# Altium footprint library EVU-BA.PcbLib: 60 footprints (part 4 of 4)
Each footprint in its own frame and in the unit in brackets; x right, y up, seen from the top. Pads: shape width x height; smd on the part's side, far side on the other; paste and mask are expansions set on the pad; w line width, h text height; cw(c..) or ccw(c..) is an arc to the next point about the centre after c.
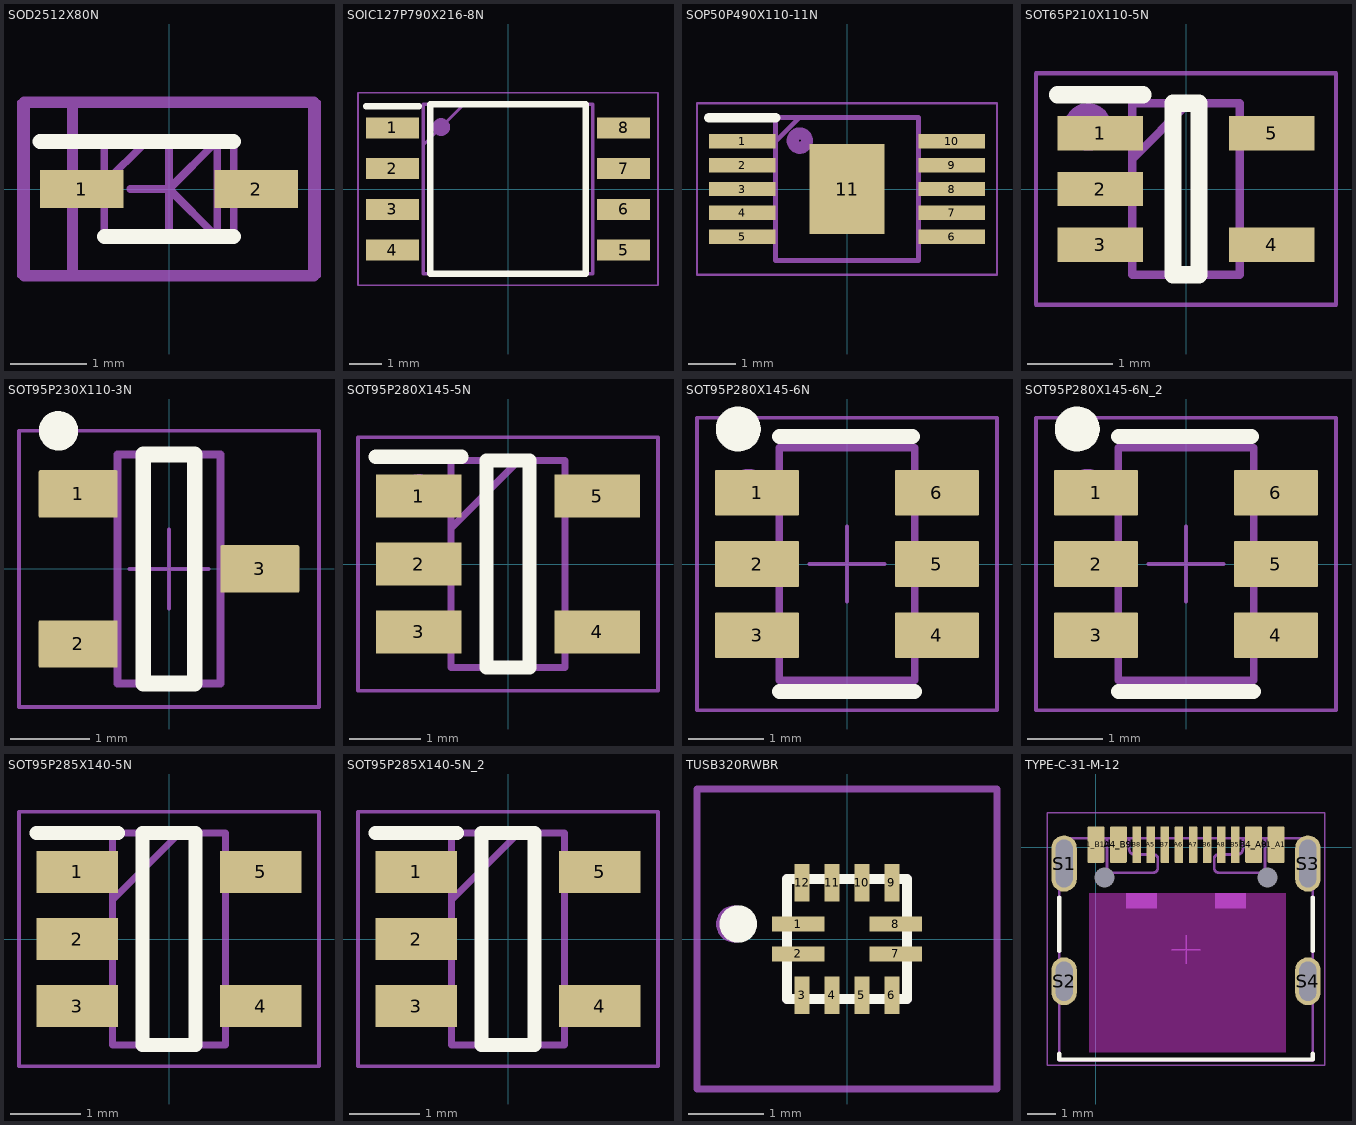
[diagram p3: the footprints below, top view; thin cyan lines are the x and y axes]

## SOD2512X80N [mm]
pads (2):
  rect 1.1x0.5 smd: 1(-1.15,0) 2(1.15,0)
Top Overlay:
  lines w0.2: -1.7,0.625 0.85,0.625 ; -0.85,-0.625 0.85,-0.625
Top Assembly:
  lines w0.1: -0.508,0 0,0 ; 0,-0.635 0,0.635 ; 0.635,0 1.143,0 ; 0,0 0.635,0.635 0.635,-0.635 0,0
  lines w0.15: -1.27,-1.143 -1.27,1.143 ; -1.905,-1.143 1.905,-1.143 1.905,1.143 -1.905,1.143 -1.905,-1.143
Mechanical 13:
  lines w0.1: -0.85,0.075 -0.3,0.625 ; -0.85,-0.625 0.85,-0.625 0.85,0.625 -0.85,0.625 -0.85,-0.625
Top Courtyard:
  lines w0.05: -1.975,-1.15 1.975,-1.15 1.975,1.15 -1.975,1.15 -1.975,-1.15
3D body "BZX84J-B4V7.stp": height 0.8, standoff 0, extent -1.25,-0.625 1.25,0.625

## SOIC127P790X216-8N [mm]
pads (8):
  rect 1.65x0.65 smd: 1(-3.6,1.905) 2(-3.6,0.635) 3(-3.6,-0.635) 4(-3.6,-1.905) 5(3.6,-1.905) 6(3.6,-0.635) 7(3.6,0.635) 8(3.6,1.905)
Top Overlay:
  lines w0.2: -4.425,2.58 -2.775,2.58 ; -2.425,-2.642 2.425,-2.642 2.425,2.642 -2.425,2.642 -2.425,-2.642
Top Assembly:
  circle w0.254: c-2.083,1.93 r0.15
  lines w0.1: -2.642,-2.642 2.642,-2.642 2.642,2.642 -2.642,2.642 -2.642,-2.642
Mechanical 13:
  lines w0.1: -2.642,1.372 -1.372,2.642 ; -2.642,-2.642 2.642,-2.642 2.642,2.642 -2.642,2.642 -2.642,-2.642
Top Courtyard:
  lines w0.05: -4.675,-2.995 4.675,-2.995 4.675,2.995 -4.675,2.995 -4.675,-2.995
3D body "MT25QL128ABA1ESE-0SIT_TR.stp": height 2.16, standoff 0, extent -3.95,-2.642 3.95,2.642

## SOP50P490X110-11N [mm]
pads (11):
  rect 1.4x0.3 smd: 1(-2.2,1) 2(-2.2,0.5) 3(-2.2,0) 4(-2.2,-0.5) 5(-2.2,-1) 6(2.2,-1) 7(2.2,-0.5) 8(2.2,0) 9(2.2,0.5) 10(2.2,1)
  rect 1.57x1.88 smd: 11(0,0)
Top Overlay:
  lines w0.2: -2.9,1.5 -1.5,1.5
Top Assembly:
  circle w0.254: c-0.991,1.016 r0.15
  lines w0.1: -1.5,-1.5 1.5,-1.5 1.5,1.5 -1.5,1.5 -1.5,-1.5
Mechanical 13:
  lines w0.1: -1.5,1 -1,1.5 ; -1.5,-1.5 1.5,-1.5 1.5,1.5 -1.5,1.5 -1.5,-1.5
Top Courtyard:
  lines w0.05: -3.15,-1.8 3.15,-1.8 3.15,1.8 -3.15,1.8 -3.15,-1.8
3D body "TPS54160DGQ.stp": height 0.96, standoff 0, extent -2.463,-1.5 2.463,1.5

## SOT65P210X110-5N [mm]
pads (5):
  rect 1x0.4 smd: 1(-1,0.65) 2(-1,0) 3(-1,-0.65) 4(1,-0.65) 5(1,0.65)
Top Overlay:
  lines w0.2: -1.5,1.1 -0.5,1.1 ; -0.15,-1 -0.15,1 0.15,1 0.15,-1 -0.15,-1
Top Assembly:
  circle w0.254: c-1.145,0.724 r0.15
  lines w0.1: -0.625,-1 -0.625,1 0.625,1 0.625,-1 -0.625,-1
Mechanical 13:
  lines w0.1: -0.625,0.35 0.025,1 ; -0.625,-1 -0.625,1 0.625,1 0.625,-1 -0.625,-1
Top Courtyard:
  lines w0.05: -1.75,-1.35 -1.75,1.35 1.75,1.35 1.75,-1.35 -1.75,-1.35
3D body "ZXRE160H5TA.stp": height 1.1, standoff 0, extent -1.05,-1 1.05,1

## SOT95P230X110-3N [mm] "SOT95P230X110-3N"
height 1.1
pads (3):
  rrect5% 1x0.6 smd mask+0.05: 1(-1.15,0.95) 2(-1.15,-0.95) 3(1.15,0)
Top Overlay:
  circle w0.25: c-1.4,1.75 r0.125
  lines w0.2: -0.325,-1.45 -0.325,1.45 0.325,1.45 0.325,-1.45 -0.325,-1.45
Top Assembly:
  circle w0.254: c-1.143,0.965 r0.15
  lines w0.1: -0.65,-1.45 -0.65,1.45 0.65,1.45 0.65,-1.45 -0.65,-1.45
Top Designator:
  text ".Designator" at -3.378,-0.211 h1.5
Mechanical 9:
  text ".MARK" at 0.329,-1.778 h1.5
Top Courtyard:
  lines w0.05: -0.5,0 0.5,0 ; 0,-0.5 0,0.5 ; -1.9,-1.75 -1.9,1.75 1.9,1.75 1.9,-1.75 -1.9,-1.75
3D body "SOT-23.STEP": height 1.1, standoff 0, extent -1.35,-1.55 1.35,1.55

## SOT95P280X145-5N [mm]
pads (5):
  rect 1.2x0.6 smd: 1(-1.25,0.95) 2(-1.25,0) 3(-1.25,-0.95) 4(1.25,-0.95) 5(1.25,0.95)
Top Overlay:
  lines w0.2: -1.85,1.5 -0.65,1.5 ; -0.3,-1.45 -0.3,1.45 0.3,1.45 0.3,-1.45 -0.3,-1.45
Top Assembly:
  circle w0.254: c-1.249,0.98 r0.15
  lines w0.1: -0.8,-1.45 -0.8,1.45 0.8,1.45 0.8,-1.45 -0.8,-1.45
Mechanical 13:
  lines w0.1: -0.8,0.5 0.15,1.45 ; -0.8,-1.45 -0.8,1.45 0.8,1.45 0.8,-1.45 -0.8,-1.45
Top Courtyard:
  lines w0.05: -2.1,-1.775 -2.1,1.775 2.1,1.775 2.1,-1.775 -2.1,-1.775
3D body "LMV331IDBVR.stp": height 1.2, standoff 0, extent -1.4,-1.45 1.4,1.45

## SOT95P280X145-6N [mm]
pads (6):
  rrect5% 1.12x0.61 smd mask+0.05: 1(-1.2,0.95) 2(-1.2,0) 3(-1.2,-0.95) 4(1.2,-0.95) 5(1.2,0) 6(1.2,0.95)
Top Overlay:
  circle w0.3: c-1.45,1.8 r0.15
  lines w0.2: -0.9,-1.7 0.9,-1.7 ; -0.9,1.7 0.875,1.7
Top Assembly:
  circle w0.254: c-1.317,0.991 r0.15
  lines w0.1: -0.9,-1.55 -0.9,1.55 0.9,1.55 0.9,-1.55 -0.9,-1.55
Top Designator:
  text ".Designator" at -3.25,-0.3 h1.5
Mechanical 9:
  text ".MARK" at 0.45,-1.675 h1.5
Top Courtyard:
  lines w0.05: -0.5,0 0.5,0 ; 0,-0.5 0,0.5 ; -2,-1.95 -2,1.95 2,1.95 2,-1.95 -2,-1.95
3D body "SOT-23-6_DBV.STEP": height 1.45, standoff 0, extent -1.417,-1.55 1.418,1.55
3D body: height 1.46, standoff 1.45, extent -0.498,0.801 0,1.3

## SOT95P280X145-6N_2 [mm]
pads (6):
  rrect5% 1.12x0.61 smd mask+0.05: 1(-1.2,0.95) 2(-1.2,0) 3(-1.2,-0.95) 4(1.2,-0.95) 5(1.2,0) 6(1.2,0.95)
Top Overlay:
  circle w0.3: c-1.45,1.8 r0.15
  lines w0.2: -0.9,-1.7 0.9,-1.7 ; -0.9,1.7 0.875,1.7
Top Assembly:
  circle w0.254: c-1.317,0.991 r0.15
  lines w0.1: -0.9,-1.55 -0.9,1.55 0.9,1.55 0.9,-1.55 -0.9,-1.55
Top Designator:
  text ".Designator" at -3.25,-0.3 h1.5
Mechanical 9:
  text ".MARK" at 0.45,-1.675 h1.5
Top Courtyard:
  lines w0.05: -0.5,0 0.5,0 ; 0,-0.5 0,0.5 ; -2,-1.95 -2,1.95 2,1.95 2,-1.95 -2,-1.95
3D body "SOT-23-6_DBV.STEP": height 1.45, standoff 0, extent -1.417,-1.55 1.418,1.55
3D body: height 1.46, standoff 1.45, extent -0.498,0.801 0,1.3

## SOT95P285X140-5N [mm]
pads (5):
  rect 1.15x0.6 smd: 1(-1.3,0.95) 2(-1.3,0) 3(-1.3,-0.95) 4(1.3,-0.95) 5(1.3,0.95)
Top Overlay:
  lines w0.2: -1.875,1.5 -0.725,1.5 ; -0.375,-1.5 0.375,-1.5 0.375,1.5 -0.375,1.5 -0.375,-1.5
Top Assembly:
  circle w0.254: c-1.254,0.939 r0.15
  lines w0.1: -0.8,-1.5 0.8,-1.5 0.8,1.5 -0.8,1.5 -0.8,-1.5
Mechanical 13:
  lines w0.1: -0.8,0.55 0.15,1.5 ; -0.8,-1.5 0.8,-1.5 0.8,1.5 -0.8,1.5 -0.8,-1.5
Top Courtyard:
  lines w0.05: -2.125,-1.8 2.125,-1.8 2.125,1.8 -2.125,1.8 -2.125,-1.8
3D body "AP2191WG-7.stp": height 1.4, standoff 0, extent -1.425,-1.5 1.425,1.5

## SOT95P285X140-5N_2 [mm]
pads (5):
  rect 1.15x0.6 smd: 1(-1.3,0.95) 2(-1.3,0) 3(-1.3,-0.95) 4(1.3,-0.95) 5(1.3,0.95)
Top Overlay:
  lines w0.2: -1.875,1.5 -0.725,1.5 ; -0.375,-1.5 0.375,-1.5 0.375,1.5 -0.375,1.5 -0.375,-1.5
Top Assembly:
  circle w0.254: c-1.254,0.939 r0.15
  lines w0.1: -0.8,-1.5 0.8,-1.5 0.8,1.5 -0.8,1.5 -0.8,-1.5
Mechanical 13:
  lines w0.1: -0.8,0.55 0.15,1.5 ; -0.8,-1.5 0.8,-1.5 0.8,1.5 -0.8,1.5 -0.8,-1.5
Top Courtyard:
  lines w0.05: -2.125,-1.8 2.125,-1.8 2.125,1.8 -2.125,1.8 -2.125,-1.8
3D body "AP2191WG-7.stp": height 1.4, standoff 0, extent -1.425,-1.5 1.425,1.5

## TUSB320RWBR [mm]
pads (12):
  rect 0.7x0.2 smd: 1(-0.65,0.2) 2(-0.65,-0.2) 7(0.65,-0.2) 8(0.65,0.2)
  rect 0.2x0.5 smd: 3(-0.6,-0.75) 4(-0.2,-0.75) 5(0.2,-0.75) 6(0.6,-0.75) 9(0.6,0.75) 10(0.2,0.75) 11(-0.2,0.75) 12(-0.6,0.75)
Top Overlay:
  lines w0.127: -0.8,-0.8 0.8,-0.8 0.8,0.8 -0.8,0.8 -0.8,-0.8
  lines w0.25: -1.575,0.2 cw(c-1.45,0.2) -1.325,0.2 cw(c-1.45,0.2) -1.575,0.2
Top Assembly:
  circle w0.254: c-1.5,0.2 r0.12
  lines w0.127: -0.8,-0.8 -0.8,0.8 0.8,0.8 0.8,-0.8 -0.8,-0.8
Mechanical 13:
  lines w0.1: -0.8,-0.8 0.8,-0.8 0.8,0.8 -0.8,0.8 -0.8,-0.8
Top Courtyard:
  lines w0.1: -2,-2 2,-2 2,2 -2,2 -2,-2
3D body "TUSB320RWBR.stp": height 0.5, standoff 0, extent -0.8,-0.8 0.8,0.8

## TYPE-C-31-M-12 [mm] "USB TYPE-C 5A 16P Female SMD USB Connectors"
height 3.24
pads (18):
  rrect15% 0.6x1.3 smd mask+0.05: A1_B12(0,0.1) A4_B9(0.8,0.1) B1_A12(6.4,0.1) B4_A9(5.6,0.1)
  rrect15% 0.3x1.3 smd mask+0.05: A5(1.95,0.1) A6(2.95,0.1) A7(3.45,0.1) A8(4.45,0.1) B5(4.95,0.1) B6(3.95,0.1) B7(2.45,0.1) B8(1.45,0.1)
  oval 0.9x2 hole 0.6 slot 1.7 at 90 deg mask+0.05: S1(-1.125,-0.57) S3(7.525,-0.57)
  oval 0.9x1.7 hole 0.6 slot 1.4 at 90 deg mask+0.05: S2(-1.125,-4.75) S4(7.525,-4.75)
  round 0 hole 0.7 unplated: ""(0.31,-1.07) ""(6.09,-1.07)
Top Layer keep-out:
  rectangle: -0.25,-7.275 6.75,-1.625
Top Overlay:
  lines w0.15: -1.3,-7.32 -1.3,-7.53 7.7,-7.53 7.7,-7.32 ; -1.3,-3.675 -1.3,-1.775 ; 7.7,-3.675 7.7,-1.775
Top Assembly:
  region: 5.325,-1.625 4.225,-1.625 4.225,-2.175 5.325,-2.175
  region: -1.3,-4.18 -1.3,-5.28 -0.875,-5.28 -0.875,-4.18
  region: 7.275,-4.194 7.275,-5.294 7.7,-5.294 7.7,-4.194
  region: 7.275,-0.022 7.275,-1.122 7.7,-1.122 7.7,-0.022
  region: -1.3,-0.024 -1.3,-1.124 -0.875,-1.124 -0.875,-0.024
  rectangle: 1.075,-2.175 2.175,-1.625
  rectangle: 4.822,0.325 5.065,0.65
  rectangle: 4.321,0.325 4.564,0.65
  rectangle: 3.828,0.325 4.071,0.65
  rectangle: 3.325,0.325 3.568,0.65
  rectangle: 2.834,0.325 3.077,0.65
  rectangle: 2.341,0.325 2.584,0.65
  rectangle: 1.825,0.325 2.068,0.65
  rectangle: 1.325,0.325 1.567,0.65
  rectangle: -0.238,0.325 0.235,0.65
  rectangle: 0.556,0.325 1.029,0.65
  rectangle: 5.365,0.325 5.838,0.65
  rectangle: 6.2,0.325 6.673,0.65
  lines w0.1: 0.4,0.3 0.4,-0.701 ccw(c0.599,-0.701) 0.599,-0.9 ; 1.182,0.325 1.182,-0.057 ccw(c1.375,-0.057) 1.375,-0.25 ; 5.218,0.325 5.218,-0.057 cw(c5.025,-0.057) 5.025,-0.25 ; 6,0.3 6,-0.701 cw(c5.801,-0.701) 5.801,-0.9 ; 0.599,-0.9 2.025,-0.9 ; 0.599,-0.9 2.025,-0.9 ; 1.375,-0.25 2.05,-0.25 ; 1.375,-0.25 1.475,-0.25 2.05,-0.25 ; 2.025,-0.9 ccw(c2.025,-0.725) 2.2,-0.725 ; 2.05,-0.25 cw(c2.05,-0.4) 2.2,-0.4 ; 2.2,-0.725 2.2,-0.4 ; 2.2,-0.725 2.2,-0.4 ; 4.2,-0.725 ccw(c4.375,-0.725) 4.375,-0.9 ; 4.2,-0.725 4.2,-0.4 ; 4.2,-0.725 4.2,-0.4 ; 4.2,-0.4 cw(c4.35,-0.4) 4.35,-0.25 ; 4.35,-0.25 5.025,-0.25 ; 4.35,-0.25 4.925,-0.25 5.025,-0.25 ; 4.375,-0.9 5.801,-0.9 ; 4.375,-0.9 5.801,-0.9 ; -1.3,-7.575 7.7,-7.575 7.7,0.325 -1.3,0.325 -1.3,-7.575
  text ".Designator" at -0.55,-3.65 h2
Top Courtyard:
  lines w0.05: 2.7,-3.625 3.7,-3.625 ; 3.2,-4.125 3.2,-3.125 ; -1.725,-7.725 8.125,-7.725 8.125,1.225 -1.725,1.225 -1.725,-7.725
Top Value:
  text ".Comment" at -0.602,-4.403 h1.5
3D body "HRO_TYPE-C-31-M-12.step": height 3.16, standoff -1.04, extent -1.275,-7.35 7.675,0.55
